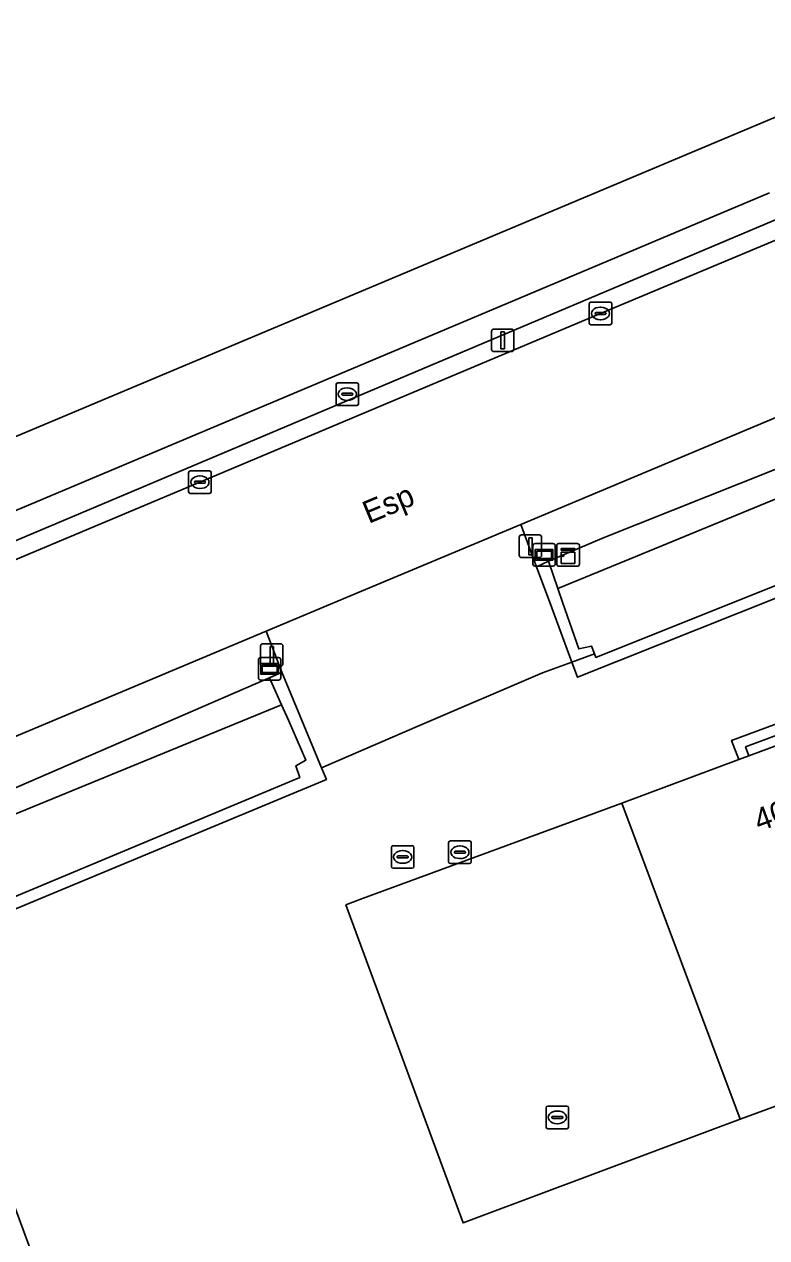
# Model space of a CAD drawing. Extents: x 161385 to 162589, y 388479 to 389756.
# Drawn here: x 162058.4 to 162091.3, y 388775.6 to 388829.4 of the extents above; entities that cross this region are included whole.
import ezdxf

# ---------------------------------------------------------------- set-up
doc = ezdxf.new("R2010")
doc.units = 0
for name, color, linetype in [('IMGEO_Afsluitpaal', 7, 'Continuous'), ('IMGEO_Berm_groen', 7, 'Continuous'), ('IMGEO_Brandkraan', 7, 'Continuous'), ('IMGEO_Erf', 7, 'Continuous'), ('IMGEO_Groenvoorziening', 7, 'Continuous'), ('IMGEO_Informatiebord', 7, 'Continuous'), ('IMGEO_Kast', 7, 'Continuous'), ('IMGEO_Kolk', 7, 'Continuous'), ('IMGEO_Lichtmast', 7, 'Continuous'), ('IMGEO_Muur', 7, 'Continuous'), ('IMGEO_Oever', 7, 'Continuous'), ('IMGEO_Openbare_ruimte_label', 7, 'Continuous'), ('IMGEO_Pand', 7, 'Continuous'), ('IMGEO_Pand_nummerreeks', 7, 'Continuous'), ('IMGEO_Pand_overbouw', 7, 'Continuous'), ('IMGEO_Rijbaan_lokaal_gesloten', 7, 'Continuous'), ('IMGEO_Voetpad_open', 7, 'Continuous'), ('IMGEO_Waterloop', 7, 'Continuous')]:
    doc.layers.add(name, color=color, linetype=linetype)

msp = doc.modelspace()

# ---------------------------------------------------------------- linework, layer by layer
at = {"layer": 'IMGEO_Afsluitpaal'}
for p, q in [((162080.459, 388806.788), (162081.249, 388806.788)), ((162081.249, 388806.788), (162080.459, 388806.788)), ((162080.359, 388805.888), (162080.359, 388806.688)), ((162080.359, 388806.688), (162080.359, 388805.888)), ((162081.349, 388806.688), (162081.349, 388805.888)), ((162081.349, 388805.888), (162081.349, 388806.688)), ((162081.249, 388805.788), (162080.459, 388805.788)), ((162080.459, 388805.788), (162081.249, 388805.788)), ((162068.884, 388801.069), (162068.884, 388801.869)), ((162068.884, 388801.869), (162068.884, 388801.069)), ((162068.984, 388801.969), (162069.774, 388801.969)), ((162069.774, 388801.969), (162068.984, 388801.969)), ((162069.874, 388801.869), (162069.874, 388801.069)), ((162069.874, 388801.069), (162069.874, 388801.869)), ((162069.774, 388800.969), (162068.984, 388800.969)), ((162068.984, 388800.969), (162069.774, 388800.969))]:
    msp.add_line(p, q, dxfattribs=at)
for points in [[(162080.779, 388806.663), (162080.929, 388806.663), (162080.929, 388805.913), (162080.779, 388805.913), (162080.779, 388806.663)], [(162069.304, 388801.844), (162069.454, 388801.844), (162069.454, 388801.094), (162069.304, 388801.094), (162069.304, 388801.844)]]:
    msp.add_lwpolyline(points, dxfattribs=at)
for centre, start, end in [((162080.459, 388806.688), 90, 180), ((162080.459, 388806.688), 90, 180), ((162081.249, 388806.688), 0, 90), ((162081.249, 388806.688), 360, 90), ((162080.459, 388805.888), 180, 270), ((162080.459, 388805.888), 180, 270), ((162081.249, 388805.888), 270, 0), ((162081.249, 388805.888), 270, 0), ((162068.984, 388801.869), 90, 180), ((162068.984, 388801.869), 90, 180), ((162069.774, 388801.869), 0, 90), ((162069.774, 388801.869), 360, 90), ((162068.984, 388801.069), 180, 270), ((162068.984, 388801.069), 180, 270), ((162069.774, 388801.069), 270, 0), ((162069.774, 388801.069), 270, 0)]:
    msp.add_arc(centre, 0.1, start, end, dxfattribs=at)
at = {"layer": 'IMGEO_Berm_groen'}
for points in [[(162091.936, 388820.838), (162051.101, 388803.612), (162049.152, 388802.833)], [(162050.467, 388802.522), (162066.195, 388809.127), (162083.964, 388816.605), (162092.793, 388820.3)]]:
    msp.add_lwpolyline(points, dxfattribs=at)
msp.add_lwpolyline([(162069.544, 388800.58), (162069.823, 388800.704), (162069.13, 388802.525), (162051.757, 388795.247), (162052.609, 388793.254)], close=True, dxfattribs=at)
at = {"layer": 'IMGEO_Brandkraan'}
for p, q in [((162072.231, 388812.604), (162072.231, 388813.456)), ((162072.306, 388813.53), (162073.158, 388813.53)), ((162072.719, 388813.31), (162072.744, 388813.31)), ((162073.232, 388813.456), (162073.232, 388812.604)), ((162072.49, 388813.024), (162072.49, 388813.036)), ((162072.928, 388812.987), (162072.53, 388812.987)), ((162072.533, 388813.073), (162072.931, 388813.073)), ((162072.742, 388812.75), (162072.717, 388812.75)), ((162072.974, 388813.036), (162072.974, 388813.024)), ((162073.158, 388812.53), (162072.306, 388812.53)), ((162074.685, 388792.094), (162074.685, 388792.946)), ((162074.76, 388793.02), (162075.612, 388793.02)), ((162075.173, 388792.8), (162075.198, 388792.8)), ((162075.686, 388792.946), (162075.686, 388792.094)), ((162074.944, 388792.514), (162074.944, 388792.526)), ((162075.382, 388792.477), (162074.984, 388792.477)), ((162074.987, 388792.563), (162075.385, 388792.563)), ((162075.196, 388792.24), (162075.171, 388792.24)), ((162075.428, 388792.526), (162075.428, 388792.514)), ((162075.612, 388792.02), (162074.76, 388792.02))]:
    msp.add_line(p, q, dxfattribs=at)
for points in [[(162072.231, 388812.604), (162072.231, 388813.456)], [(162072.306, 388813.53), (162073.158, 388813.53)], [(162073.232, 388813.456), (162073.232, 388812.604)], [(162073.158, 388812.53), (162072.306, 388812.53)], [(162074.685, 388792.094), (162074.685, 388792.946)], [(162074.76, 388793.02), (162075.612, 388793.02)], [(162075.686, 388792.946), (162075.686, 388792.094)], [(162075.612, 388792.02), (162074.76, 388792.02)]]:
    msp.add_lwpolyline(points, dxfattribs=at)
for centre, radius, start, end in [((162072.308, 388813.454), 0.0765, 91.552, 178.448), ((162072.308, 388813.454), 0.0765, 91.552, 178.448), ((162073.156, 388813.454), 0.0765, 1.552, 88.448), ((162073.156, 388813.454), 0.0765, 1.552, 88.448), ((162072.53, 388813.033), 0.0403, 85.8775, 175.7526), ((162072.527, 388813.023), 0.0366, 178.938, 274.7102), ((162072.931, 388813.03), 0.043, 264.8664, 352.4533), ((162072.935, 388813.035), 0.0386, 1.7309, 96.639), ((162072.308, 388812.606), 0.0765, 181.552, 268.448), ((162072.308, 388812.606), 0.0765, 181.552, 268.448), ((162073.156, 388812.606), 0.0765, 271.552, 358.448), ((162073.156, 388812.606), 0.0765, 271.552, 358.448), ((162074.762, 388792.944), 0.0765, 91.552, 178.448), ((162074.762, 388792.944), 0.0765, 91.552, 178.448), ((162075.61, 388792.944), 0.0765, 1.552, 88.448), ((162075.61, 388792.944), 0.0765, 1.552, 88.448), ((162074.984, 388792.523), 0.0403, 85.8775, 175.7526), ((162074.981, 388792.513), 0.0366, 178.938, 274.7102), ((162075.385, 388792.52), 0.043, 264.8664, 352.4533), ((162075.389, 388792.525), 0.0386, 1.7309, 96.639), ((162074.762, 388792.096), 0.0765, 181.552, 268.448), ((162074.762, 388792.096), 0.0765, 181.552, 268.448), ((162075.61, 388792.096), 0.0765, 271.552, 358.448), ((162075.61, 388792.096), 0.0765, 271.552, 358.448)]:
    msp.add_arc(centre, radius, start, end, dxfattribs=at)
for centre, major_axis, ratio, start_param, end_param in [((162072.718, 388813.03), (-0.387, 0.002), 0.722429, 4.712389, 7.853982), ((162072.743, 388813.03), (-0.39, 0.002), 0.717154, 1.570796, 4.712389), ((162075.172, 388792.52), (-0.387, 0.002), 0.722429, 4.712389, 7.853982), ((162075.197, 388792.52), (-0.39, 0.002), 0.717154, 1.570796, 4.712389)]:
    msp.add_ellipse(centre, major_axis=major_axis, ratio=ratio, start_param=start_param, end_param=end_param, dxfattribs=at)
at = {"layer": 'IMGEO_Erf'}
for points in [[(162113.978, 388789.645), (162090.149, 388780.9), (162084.904, 388794.91), (162090.089, 388796.832), (162089.771, 388797.682), (162120.964, 388809.223)], [(162120.333, 388808.51), (162090.394, 388797.404), (162090.544, 388797), (162117.872, 388807.131)], [(162100.979, 388807.667), (162082.944, 388800.482), (162082.695, 388801.152), (162081.388, 388800.675), (162075.936, 388798.339), (162071.588, 388796.475), (162071.804, 388795.956), (162037.233, 388781.575), (162036.191, 388781.141), (162035.905, 388781.533), (162034.728, 388780.978), (162034.719, 388780.973), (162034.772, 388780.32), (162037.878, 388771.394), (162041.72, 388760.779), (162051.927, 388733.275), (162056.227, 388721.385), (162060.26, 388709.472), (162067.129, 388690.346), (162069.681, 388682.58), (162072.391, 388674.979), (162073.83, 388675.414), (162119.716, 388689.275)]]:
    msp.add_lwpolyline(points, dxfattribs=at)
msp.add_lwpolyline([(162065.669, 388750), (162066.202, 388748.564), (162054.165, 388744.117), (162051.983, 388750), (162051.56, 388751.141), (162044.081, 388771.555), (162042.814, 388774.988), (162041.363, 388778.904), (162042.412, 388779.283), (162042.532, 388778.983), (162054.417, 388783.358), (162054.316, 388783.692), (162055.373, 388784.083), (162063.149, 388762.982), (162061.118, 388762.233), (162063.596, 388755.586)], close=True, dxfattribs=at)
at = {"layer": 'IMGEO_Groenvoorziening'}
for points in [[(162093.508, 388826.06), (162048.347, 388807.09), (162045.228, 388813.835), (162038.345, 388810.652), (162035.583, 388816.547)], [(162048.684, 388803.926), (162050.304, 388804.628), (162091.45, 388821.953)], [(162097.873, 388814.565), (162080.428, 388807.257), (162081.118, 388805.384), (162081.649, 388805.633), (162084.128, 388806.673), (162105.294, 388815.098)]]:
    msp.add_lwpolyline(points, dxfattribs=at)
at = {"layer": 'IMGEO_Informatiebord'}
for p, q in [((162080.964, 388805.511), (162080.964, 388806.311)), ((162080.964, 388806.311), (162080.964, 388805.511)), ((162081.064, 388806.411), (162081.854, 388806.411)), ((162081.854, 388806.411), (162081.064, 388806.411)), ((162081.954, 388806.311), (162081.954, 388805.511)), ((162081.954, 388805.511), (162081.954, 388806.311)), ((162081.854, 388805.411), (162081.064, 388805.411)), ((162081.064, 388805.411), (162081.854, 388805.411)), ((162068.889, 388801.355), (162069.679, 388801.355)), ((162069.679, 388801.355), (162068.889, 388801.355)), ((162068.789, 388800.455), (162068.789, 388801.255)), ((162068.789, 388801.255), (162068.789, 388800.455)), ((162069.779, 388801.255), (162069.779, 388800.455)), ((162069.779, 388800.455), (162069.779, 388801.255)), ((162069.679, 388800.355), (162068.889, 388800.355)), ((162068.889, 388800.355), (162069.679, 388800.355))]:
    msp.add_line(p, q, dxfattribs=at)
for points in [[(162081.065, 388806.143), (162081.853, 388806.143), (162081.853, 388805.679), (162081.065, 388805.679), (162081.065, 388806.143)], [(162081.13, 388806.078), (162081.13, 388805.744), (162081.788, 388805.744), (162081.788, 388806.078), (162081.13, 388806.078)], [(162068.89, 388801.087), (162069.678, 388801.087), (162069.678, 388800.623), (162068.89, 388800.623), (162068.89, 388801.087)], [(162068.955, 388801.022), (162068.955, 388800.688), (162069.613, 388800.688), (162069.613, 388801.022), (162068.955, 388801.022)]]:
    msp.add_lwpolyline(points, dxfattribs=at)
for centre, start, end in [((162081.064, 388806.311), 90, 180), ((162081.064, 388806.311), 90, 180), ((162081.854, 388806.311), 0, 90), ((162081.854, 388806.311), 360, 90), ((162081.064, 388805.511), 180, 270), ((162081.064, 388805.511), 180, 270), ((162081.854, 388805.511), 270, 0), ((162081.854, 388805.511), 270, 0), ((162068.889, 388801.255), 90, 180), ((162068.889, 388801.255), 90, 180), ((162069.679, 388801.255), 0, 90), ((162069.679, 388801.255), 360, 90), ((162068.889, 388800.455), 180, 270), ((162068.889, 388800.455), 180, 270), ((162069.679, 388800.455), 270, 0), ((162069.679, 388800.455), 270, 0)]:
    msp.add_arc(centre, 0.1, start, end, dxfattribs=at)
at = {"layer": 'IMGEO_Kast'}
for p, q in [((162082.025, 388805.481), (162082.025, 388806.322)), ((162082.025, 388806.322), (162082.025, 388805.481)), ((162082.1, 388806.406), (162082.941, 388806.406)), ((162082.941, 388806.406), (162082.1, 388806.406)), ((162083.025, 388806.331), (162083.025, 388805.49)), ((162083.025, 388805.49), (162083.025, 388806.331)), ((162082.95, 388805.406), (162082.109, 388805.406)), ((162082.109, 388805.406), (162082.95, 388805.406))]:
    msp.add_line(p, q, dxfattribs=at)
for points in [[(162082.22, 388806.196), (162082.82, 388806.196), (162082.82, 388806.111), (162082.22, 388806.111), (162082.22, 388806.196)], [(162082.22, 388806.021), (162082.82, 388806.021), (162082.82, 388805.532), (162082.22, 388805.532), (162082.22, 388806.021)]]:
    msp.add_lwpolyline(points, dxfattribs=at)
msp.add_circle((162082.304, 388805.87), 0.0377, dxfattribs=at)
for centre, start, end in [((162082.103, 388806.328), 92.4484, 184.2845), ((162082.103, 388806.328), 92.4484, 184.2845), ((162082.947, 388806.328), 2.4484, 94.2845), ((162082.947, 388806.328), 2.4484, 94.2845), ((162082.103, 388805.484), 182.4484, 274.2845), ((162082.103, 388805.484), 182.4484, 274.2845), ((162082.947, 388805.484), 272.4484, 4.2845), ((162082.947, 388805.484), 272.4484, 4.2845)]:
    msp.add_arc(centre, 0.0779, start, end, dxfattribs=at)
at = {"layer": 'IMGEO_Kolk'}
for p, q in [((162083.462, 388816.18), (162083.462, 388817.032)), ((162083.537, 388817.106), (162084.389, 388817.106)), ((162084.463, 388817.032), (162084.463, 388816.18)), ((162083.721, 388816.6), (162083.721, 388816.612)), ((162084.159, 388816.563), (162083.761, 388816.563)), ((162083.764, 388816.649), (162084.162, 388816.649)), ((162083.95, 388816.886), (162083.975, 388816.886)), ((162084.205, 388816.612), (162084.205, 388816.6)), ((162084.389, 388816.106), (162083.537, 388816.106)), ((162083.973, 388816.326), (162083.948, 388816.326)), ((162065.694, 388808.702), (162065.694, 388809.554)), ((162065.769, 388809.628), (162066.621, 388809.628)), ((162066.182, 388809.408), (162066.207, 388809.408)), ((162066.695, 388809.554), (162066.695, 388808.702)), ((162065.953, 388809.122), (162065.953, 388809.134)), ((162066.391, 388809.085), (162065.993, 388809.085)), ((162065.996, 388809.171), (162066.394, 388809.171)), ((162066.205, 388808.848), (162066.18, 388808.848)), ((162066.437, 388809.134), (162066.437, 388809.122)), ((162066.621, 388808.628), (162065.769, 388808.628)), ((162077.226, 388792.303), (162077.226, 388793.155)), ((162077.301, 388793.229), (162078.153, 388793.229)), ((162077.485, 388792.723), (162077.485, 388792.735)), ((162077.528, 388792.772), (162077.926, 388792.772)), ((162077.714, 388793.009), (162077.739, 388793.009)), ((162077.969, 388792.735), (162077.969, 388792.723)), ((162078.227, 388793.155), (162078.227, 388792.303)), ((162078.153, 388792.229), (162077.301, 388792.229)), ((162077.923, 388792.686), (162077.525, 388792.686)), ((162077.737, 388792.449), (162077.712, 388792.449)), ((162081.621, 388781.479), (162082.473, 388781.479)), ((162081.546, 388780.553), (162081.546, 388781.405)), ((162081.805, 388780.973), (162081.805, 388780.985)), ((162082.243, 388780.936), (162081.845, 388780.936)), ((162081.848, 388781.022), (162082.246, 388781.022)), ((162082.034, 388781.259), (162082.059, 388781.259)), ((162082.289, 388780.985), (162082.289, 388780.973)), ((162082.547, 388781.405), (162082.547, 388780.553)), ((162082.473, 388780.479), (162081.621, 388780.479)), ((162082.057, 388780.699), (162082.032, 388780.699))]:
    msp.add_line(p, q, dxfattribs=at)
for points in [[(162083.462, 388816.18), (162083.462, 388817.032)], [(162083.537, 388817.106), (162084.389, 388817.106)], [(162084.463, 388817.032), (162084.463, 388816.18)], [(162084.389, 388816.106), (162083.537, 388816.106)], [(162065.694, 388808.702), (162065.694, 388809.554)], [(162065.769, 388809.628), (162066.621, 388809.628)], [(162066.695, 388809.554), (162066.695, 388808.702)], [(162066.621, 388808.628), (162065.769, 388808.628)], [(162077.226, 388792.303), (162077.226, 388793.155)], [(162077.301, 388793.229), (162078.153, 388793.229)], [(162078.227, 388793.155), (162078.227, 388792.303)], [(162078.153, 388792.229), (162077.301, 388792.229)], [(162081.621, 388781.479), (162082.473, 388781.479)], [(162081.546, 388780.553), (162081.546, 388781.405)], [(162082.547, 388781.405), (162082.547, 388780.553)], [(162082.473, 388780.479), (162081.621, 388780.479)]]:
    msp.add_lwpolyline(points, dxfattribs=at)
for centre, radius, start, end in [((162083.539, 388817.03), 0.0765, 91.552, 178.448), ((162083.539, 388817.03), 0.0765, 91.552, 178.448), ((162084.387, 388817.03), 0.0765, 1.552, 88.448), ((162084.387, 388817.03), 0.0765, 1.552, 88.448), ((162083.761, 388816.609), 0.0403, 85.8775, 175.7526), ((162083.758, 388816.599), 0.0366, 178.938, 274.7102), ((162084.162, 388816.606), 0.043, 264.8664, 352.4533), ((162084.166, 388816.611), 0.0386, 1.7309, 96.639), ((162083.539, 388816.182), 0.0765, 181.552, 268.448), ((162083.539, 388816.182), 0.0765, 181.552, 268.448), ((162084.387, 388816.182), 0.0765, 271.552, 358.448), ((162084.387, 388816.182), 0.0765, 271.552, 358.448), ((162065.771, 388809.552), 0.0765, 91.552, 178.448), ((162065.771, 388809.552), 0.0765, 91.552, 178.448), ((162066.619, 388809.552), 0.0765, 1.552, 88.448), ((162066.619, 388809.552), 0.0765, 1.552, 88.448), ((162065.993, 388809.131), 0.0403, 85.8775, 175.7526), ((162065.99, 388809.121), 0.0366, 178.938, 274.7102), ((162066.394, 388809.128), 0.043, 264.8664, 352.4533), ((162066.398, 388809.133), 0.0386, 1.7309, 96.639), ((162065.771, 388808.704), 0.0765, 181.552, 268.448), ((162065.771, 388808.704), 0.0765, 181.552, 268.448), ((162066.619, 388808.704), 0.0765, 271.552, 358.448), ((162066.619, 388808.704), 0.0765, 271.552, 358.448), ((162077.303, 388793.153), 0.0765, 91.552, 178.448), ((162077.303, 388793.153), 0.0765, 91.552, 178.448), ((162077.525, 388792.732), 0.0403, 85.8775, 175.7526), ((162077.522, 388792.722), 0.0366, 178.938, 274.7102), ((162077.926, 388792.729), 0.043, 264.8664, 352.4533), ((162077.93, 388792.734), 0.0386, 1.7309, 96.639), ((162078.151, 388793.153), 0.0765, 1.552, 88.448), ((162078.151, 388793.153), 0.0765, 1.552, 88.448), ((162077.303, 388792.305), 0.0765, 181.552, 268.448), ((162077.303, 388792.305), 0.0765, 181.552, 268.448), ((162078.151, 388792.305), 0.0765, 271.552, 358.448), ((162078.151, 388792.305), 0.0765, 271.552, 358.448), ((162081.623, 388781.403), 0.0765, 91.552, 178.448), ((162081.623, 388781.403), 0.0765, 91.552, 178.448), ((162082.471, 388781.403), 0.0765, 1.552, 88.448), ((162082.471, 388781.403), 0.0765, 1.552, 88.448), ((162081.845, 388780.982), 0.0403, 85.8775, 175.7526), ((162081.842, 388780.972), 0.0366, 178.938, 274.7102), ((162082.246, 388780.979), 0.043, 264.8664, 352.4533), ((162082.25, 388780.984), 0.0386, 1.7309, 96.639), ((162081.623, 388780.555), 0.0765, 181.552, 268.448), ((162081.623, 388780.555), 0.0765, 181.552, 268.448), ((162082.471, 388780.555), 0.0765, 271.552, 358.448), ((162082.471, 388780.555), 0.0765, 271.552, 358.448)]:
    msp.add_arc(centre, radius, start, end, dxfattribs=at)
for centre, major_axis, ratio, start_param, end_param in [((162083.949, 388816.606), (-0.387, 0.002), 0.722429, 4.712389, 7.853982), ((162083.974, 388816.606), (-0.39, 0.002), 0.717154, 1.570796, 4.712389), ((162066.181, 388809.128), (-0.387, 0.002), 0.722429, 4.712389, 7.853982), ((162066.206, 388809.128), (-0.39, 0.002), 0.717154, 1.570796, 4.712389), ((162077.713, 388792.729), (-0.387, 0.002), 0.722429, 4.712389, 7.853982), ((162077.738, 388792.729), (-0.39, 0.002), 0.717154, 1.570796, 4.712389), ((162082.033, 388780.979), (-0.387, 0.002), 0.722429, 4.712389, 7.853982), ((162082.058, 388780.979), (-0.39, 0.002), 0.717154, 1.570796, 4.712389)]:
    msp.add_ellipse(centre, major_axis=major_axis, ratio=ratio, start_param=start_param, end_param=end_param, dxfattribs=at)
at = {"layer": 'IMGEO_Lichtmast'}
for p, q in [((162079.227, 388815.914), (162080.017, 388815.914)), ((162080.017, 388815.914), (162079.227, 388815.914)), ((162079.127, 388815.014), (162079.127, 388815.814)), ((162079.127, 388815.814), (162079.127, 388815.014)), ((162080.117, 388815.814), (162080.117, 388815.014)), ((162080.117, 388815.014), (162080.117, 388815.814)), ((162080.017, 388814.914), (162079.227, 388814.914)), ((162079.227, 388814.914), (162080.017, 388814.914))]:
    msp.add_line(p, q, dxfattribs=at)
msp.add_lwpolyline([(162079.547, 388815.789), (162079.697, 388815.789), (162079.697, 388815.039), (162079.547, 388815.039), (162079.547, 388815.789)], dxfattribs=at)
for centre, start, end in [((162079.227, 388815.814), 90, 180), ((162079.227, 388815.814), 90, 180), ((162080.017, 388815.814), 0, 90), ((162080.017, 388815.814), 360, 90), ((162079.227, 388815.014), 180, 270), ((162079.227, 388815.014), 180, 270), ((162080.017, 388815.014), 270, 0), ((162080.017, 388815.014), 270, 0)]:
    msp.add_arc(centre, 0.1, start, end, dxfattribs=at)
at = {"layer": 'IMGEO_Muur'}
for points in [[(162105.447, 388749.108), (162106.601, 388746.014), (162058.944, 388728.375), (162053.195, 388743.617), (162052.765, 388743.449), (162058.659, 388727.729), (162106.287, 388745.331), (162107.264, 388745.692), (162106.946, 388746.548), (162120.964, 388809.223), (162089.771, 388797.682), (162090.089, 388796.832), (162090.544, 388797), (162090.394, 388797.404), (162120.333, 388808.51), (162106.664, 388747.307), (162105.908, 388749.278)], [(162082.294, 388803.771), (162082.069, 388804.421), (162081.649, 388805.633), (162081.118, 388805.384), (162081.798, 388803.559), (162082.695, 388801.152), (162083.699, 388801.518), (162083.565, 388801.867), (162082.997, 388801.738)], [(162071.804, 388795.956), (162071.588, 388796.475), (162070.621, 388798.791), (162069.823, 388800.704), (162069.544, 388800.58), (162069.286, 388800.465), (162069.817, 388799.258), (162070.117, 388798.576), (162070.892, 388796.816), (162070.443, 388796.555), (162070.625, 388796.045), (162035.905, 388781.533), (162036.191, 388781.141), (162037.233, 388781.575)]]:
    msp.add_lwpolyline(points, close=True, dxfattribs=at)
msp.add_lwpolyline([(162100.792, 388808.167), (162083.759, 388801.362), (162083.699, 388801.518), (162082.695, 388801.152), (162082.944, 388800.482), (162100.979, 388807.667)], dxfattribs=at)
at = {"layer": 'IMGEO_Oever'}
msp.add_lwpolyline([(162105.294, 388815.098), (162084.128, 388806.673), (162081.649, 388805.633), (162082.069, 388804.421), (162085.348, 388805.764), (162102.46, 388812.799)], dxfattribs=at)
msp.add_lwpolyline([(162069.817, 388799.258), (162069.286, 388800.465), (162069.544, 388800.58), (162052.609, 388793.254), (162034.299, 388786.108), (162034.727, 388784.889)], close=True, dxfattribs=at)
at = {"layer": 'IMGEO_Pand'}
msp.add_lwpolyline([(162096.812, 388887.735), (162081.552, 388882.482), (162023.417, 388862.083), (162022.89, 388863.239), (162023.258, 388863.399), (162023.087, 388863.771), (162015.754, 388860.392), (162020.642, 388849.809), (162021.451, 388850.176), (162025.587, 388841.238), (162025.64, 388841.124), (162024.832, 388840.744), (162027.227, 388835.569), (162028.853, 388832.057), (162036.403, 388835.564), (162039.082, 388829.266), (162038.244, 388828.934), (162044.342, 388815.75), (162045.228, 388813.835), (162048.347, 388807.09), (162093.508, 388826.06)], dxfattribs=at)
for points in [[(162090.149, 388780.9), (162113.978, 388789.645), (162117.872, 388807.131), (162090.544, 388797), (162090.089, 388796.832), (162084.904, 388794.91)], [(162066.202, 388748.564), (162065.669, 388750), (162063.596, 388755.586), (162061.118, 388762.233), (162063.149, 388762.982), (162055.373, 388784.083), (162054.316, 388783.692), (162054.417, 388783.358), (162042.532, 388778.983), (162042.412, 388779.283), (162041.363, 388778.904), (162042.814, 388774.988), (162044.081, 388771.555), (162051.56, 388751.141), (162051.983, 388750), (162054.165, 388744.117)]]:
    msp.add_lwpolyline(points, close=True, dxfattribs=at)
at = {"layer": 'IMGEO_Pand_overbouw'}
msp.add_lwpolyline([(162084.904, 388794.91), (162083.664, 388794.453), (162073.411, 388790.673), (162072.666, 388790.398), (162077.866, 388776.304), (162078.586, 388776.573), (162088.806, 388780.397), (162090.149, 388780.9)], close=True, dxfattribs=at)
at = {"layer": 'IMGEO_Rijbaan_lokaal_gesloten'}
for points in [[(162092.793, 388820.3), (162083.964, 388816.605), (162066.195, 388809.127), (162050.467, 388802.522)], [(162051.757, 388795.247), (162069.13, 388802.525), (162072.726, 388804.031), (162080.428, 388807.257), (162097.873, 388814.565)]]:
    msp.add_lwpolyline(points, dxfattribs=at)
at = {"layer": 'IMGEO_Voetpad_open'}
msp.add_lwpolyline([(162091.45, 388821.953), (162050.304, 388804.628), (162048.684, 388803.926), (162049.152, 388802.833), (162051.101, 388803.612), (162091.936, 388820.838)], dxfattribs=at)
msp.add_lwpolyline([(162081.388, 388800.675), (162082.695, 388801.152), (162081.798, 388803.559), (162081.118, 388805.384), (162080.428, 388807.257), (162072.726, 388804.031), (162069.13, 388802.525), (162069.823, 388800.704), (162070.621, 388798.791), (162071.588, 388796.475), (162075.936, 388798.339)], close=True, dxfattribs=at)
at = {"layer": 'IMGEO_Waterloop'}
msp.add_lwpolyline([(162102.46, 388812.799), (162085.348, 388805.764), (162082.069, 388804.421), (162082.294, 388803.771), (162082.997, 388801.738), (162083.565, 388801.867), (162083.699, 388801.518), (162083.759, 388801.362), (162100.792, 388808.167)], dxfattribs=at)
msp.add_lwpolyline([(162070.625, 388796.045), (162070.443, 388796.555), (162070.892, 388796.816), (162070.117, 388798.576), (162069.817, 388799.258), (162034.727, 388784.889), (162035.54, 388782.571), (162035.905, 388781.533)], close=True, dxfattribs=at)

# ---------------------------------------------------------------- texts
at = {"layer": 'IMGEO_Openbare_ruimte_label'}
msp.add_text('Esp', height=1, rotation=22.7169, dxfattribs=at).set_placement((162073.678, 388807.274))
at = {"layer": 'IMGEO_Pand_nummerreeks'}
msp.add_text('401', height=1, rotation=20.2976, dxfattribs=at).set_placement((162090.994, 388793.633))

doc.saveas('drawing.dxf')
